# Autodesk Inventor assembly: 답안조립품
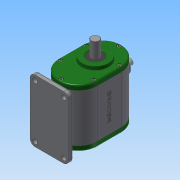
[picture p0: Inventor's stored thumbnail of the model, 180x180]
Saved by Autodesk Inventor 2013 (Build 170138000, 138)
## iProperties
Created: 2016-12
Part Number: 답안조립품
Document SubType Name: Assembly
Designer: Administrator
Mass: 2543.95 g
Surface Area: 2007.06 cm^2
Volume: 724.782 cm^3
Density: 3.50995 g/cm^3
Author: Administrator
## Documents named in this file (14)
- C:\Users\Administrator\Desktop\361208V1027\답안조립품.iam
- C:\Users\Administrator\Desktop\361208V1027\가변스프링.ipt
- C:\Users\Administrator\Desktop\361208V1027\뒤커버.ipt
- C:\Users\Administrator\Desktop\361208V1027\메인축.ipt
- C:\Users\Administrator\Desktop\361208V1027\베어링 608.ipt
- C:\Users\Administrator\Desktop\361208V1027\베어링 6003.ipt
- C:\Users\Administrator\Desktop\361208V1027\본체.ipt
- C:\Users\Administrator\Desktop\361208V1027\볼트 M4.ipt
- C:\Users\Administrator\Desktop\361208V1027\부시.ipt
- C:\Users\Administrator\Desktop\361208V1027\서브축.ipt
- C:\Users\Administrator\Desktop\361208V1027\슬라이더.ipt
- C:\Users\Administrator\Desktop\361208V1027\앞커버.ipt
- C:\Users\Administrator\Desktop\361208V1027\오일실 8 22 7.ipt
- C:\Users\Administrator\Desktop\361208V1027\오일실 17 32 8.ipt
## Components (1 placed, 1 different names)
1. 가변스프링:1
